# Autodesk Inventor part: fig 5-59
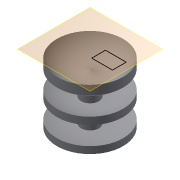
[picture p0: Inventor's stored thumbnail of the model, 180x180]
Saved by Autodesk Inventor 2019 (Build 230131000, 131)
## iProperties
Created: 2004-05
Part Number: fig 5-59
Document SubType Name: Modeling
Designer: CADCIM Technologies
Manufacturer: Standard
Standards Organization: Custom
Density: 1 g/cm^3
Material: Generic
Appearance: Default
Author: CADCIM Technologies
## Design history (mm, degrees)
sketch "Sketch1"
  geometry: L1 (0.098, 22.743)-(0.098, 0.516); L2 (-3.621, 19.305)-(-3.621, 13.061); L3 (-3.621, 10.379)-(-3.621, 3.25); L4 (-3.664, 0.516)-(0.098, 0.516); L5 (-13.694, 4.7)-(-13.694, 1.836); L6 (-13.694, 26.851)-(-13.694, 23.014); L7 (-13.694, 15.335)-(-13.694, 12.343); A1 r 10.546 centre (-4.597, 32.185) between (-13.694, 26.851) and (0.098, 22.743); A2 r 21.828 centre (-4.597, 32.185) between (-13.694, 12.343) and (-3.621, 10.379); A3 r 12.918 centre (-4.597, 32.185) between (-13.694, 23.014) and (-3.621, 19.305); A4 r 19.149 centre (-4.597, 32.185) between (-13.694, 15.335) and (-3.621, 13.061); A5 r 28.952 centre (-4.597, 32.185) between (-13.694, 4.7) and (-3.621, 3.25); A6 r 31.683 centre (-4.597, 32.185) between (-13.694, 1.836) and (-3.664, 0.516)
  constraints: 14 end point, 12 point on circle, 6 centre point, 4 perpendicular, 2 parallel, 1 vertical
revolve "Revolution1" sketch "Sketch1" stored, may be unused: angle "d0" = 90 deg
workplane "Work Plane1"
sketch "Sketch2"
  geometry: L1 (3.408, -2.846)-(12.06, -2.846); L2 (12.06, -2.846)-(12.06, 2.873); L3 (12.06, 2.873)-(3.408, 2.873); L4 (3.408, 2.873)-(3.408, -2.846)
  constraints: 8 end point, 2 parallel, 1 horizontal, 1 perpendicular
body "Solid1"
